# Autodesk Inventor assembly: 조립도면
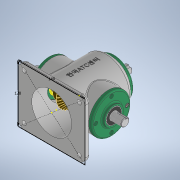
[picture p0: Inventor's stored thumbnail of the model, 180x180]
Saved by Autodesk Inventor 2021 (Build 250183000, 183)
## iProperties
Created: 2021-02
Part Number: 조립도면
Document SubType Name: Assembly
Designer: mdu2-97
Author: mdu2-97
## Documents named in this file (16)
- C:\Users\mdu2-97\Desktop\710215V1001\조립도면.iam
- C:\Users\mdu2-97\Desktop\710215V1001\본체.ipt
- C:\Users\mdu2-97\Desktop\710215V1001\커버.ipt
- C:\Users\mdu2-97\Desktop\710215V1001\베어링 6203.ipt
- C:\Users\mdu2-97\Desktop\710215V1001\메인 축.ipt
- 메인 축.ipt
- C:\Users\mdu2-97\Desktop\710215V1001\키 5x5.ipt
- C:\Users\mdu2-97\Desktop\710215V1001\메인 베벨기어.ipt
- C:\Users\mdu2-97\Desktop\710215V1001\서브 축.ipt
- 서브 축.ipt
- C:\Users\mdu2-97\Desktop\710215V1001\키 4x4.ipt
- C:\Users\mdu2-97\Desktop\710215V1001\서브 베벨기어.ipt
- C:\Users\mdu2-97\Desktop\710215V1001\볼트 M4.ipt
- 볼트 M4.ipt
- C:\Users\mdu2-97\Desktop\710215V1001\오일 실.ipt
- 오일 실.ipt
